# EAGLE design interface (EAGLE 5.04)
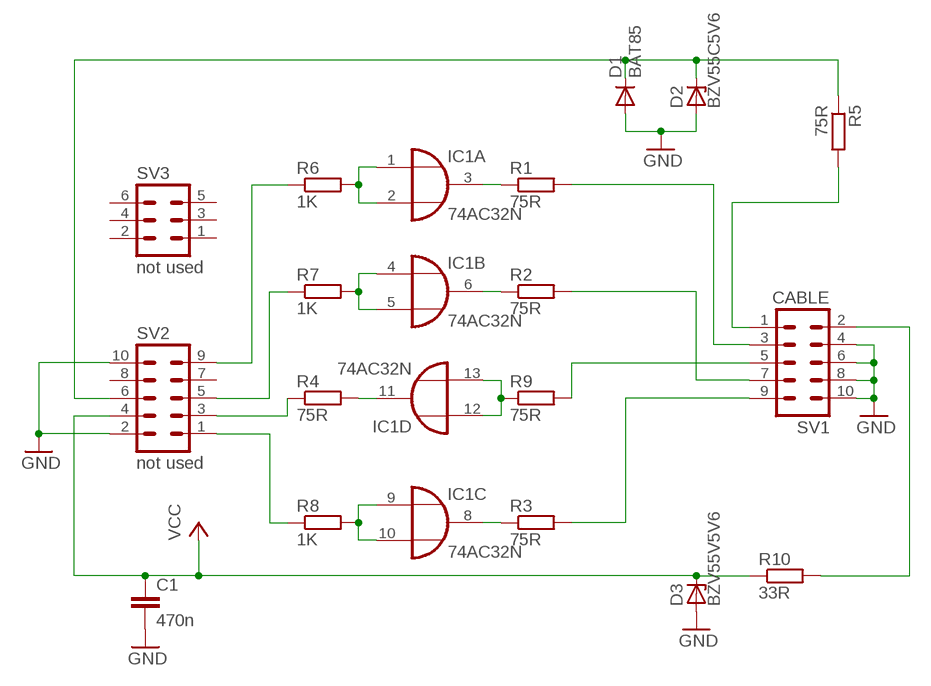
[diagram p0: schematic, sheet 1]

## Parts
C1  470n  C2.5P  [C025-030X050]
D1  BAT85  1N4148  [DO34-7]
D2  BZV55C5V6  ZENERDIODE  [DO34Z7]
D3  BZV55V5V6  ZENERDIODE  [DO34Z7]
IC1  74AC32N  [DIL14]
R1  75R  R  [0207/10]
R2  75R  R  [0207/10]
R3  75R  R  [0207/10]
R4  75R  R  [0207/10]
R5  75R  R  [0207/10]
R6  1K  R  [0207/10]
R7  1K  R  [0207/10]
R8  1K  R  [0207/10]
R9  75R  R  [0207/10]
R10  33R  R  [0207/10]
SV1  CABLE  ML10L  [ML10L]
SV2  not used  MA05-2  [MA05-2]
SV3  not used  MA03-2  [MA03-2]

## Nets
GND: C1.2 D1.A D2.A D3.A SV1.4 SV1.6 SV1.8 SV1.10 SV2.2 SV2.10
N$1: IC1.3(A:O) R1.1
N$2: IC1.6(B:O) R2.1
N$3: IC1.8(C:O) R3.1
N$4: IC1.11(D:O) R4.2
N$5: IC1.4(B:I0) IC1.5(B:I1) R7.2
N$6: IC1.12(D:I0) IC1.13(D:I1) R9.1
N$7: IC1.9(C:I0) IC1.10(C:I1) R8.2
N$8: IC1.1(A:I0) IC1.2(A:I1) R6.2
N$10: D1.C D2.C R5.1 SV2.6
N$11: R5.2 SV1.1
N$12: R1.2 SV1.3
N$13: R2.2 SV1.7
N$14: R3.2 SV1.9
N$16: R9.2 SV1.5
N$17: R6.1 SV2.9
N$18: R7.1 SV2.5
N$19: R4.1 SV2.3
N$20: R8.1 SV2.1
N$21: R10.2 SV1.2
VCC: C1.1 D3.C R10.1 SV2.4
Unconnected: SV2.7 SV2.8 SV3.1 SV3.2 SV3.3 SV3.4 SV3.5 SV3.6

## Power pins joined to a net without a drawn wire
GND: IC1.7(P:GND)
VCC: IC1.14(P:VCC)

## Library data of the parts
C1 = ee2parts:C: Capacitor
D1 = ee2parts:1N4148: DIODE
D2 D3 = ee2parts:ZENERDIODE: Z DIODE
IC1 = 74xx-eu:74*32: Quad 2-input OR gate
R1-R10 = ee2parts:R: Resistor
SV1 = con-ml:ML10L: HARTING
SV2 = con-lstb:MA05-2: PIN HEADER
SV3 = con-lstb:MA03-2: PIN HEADER

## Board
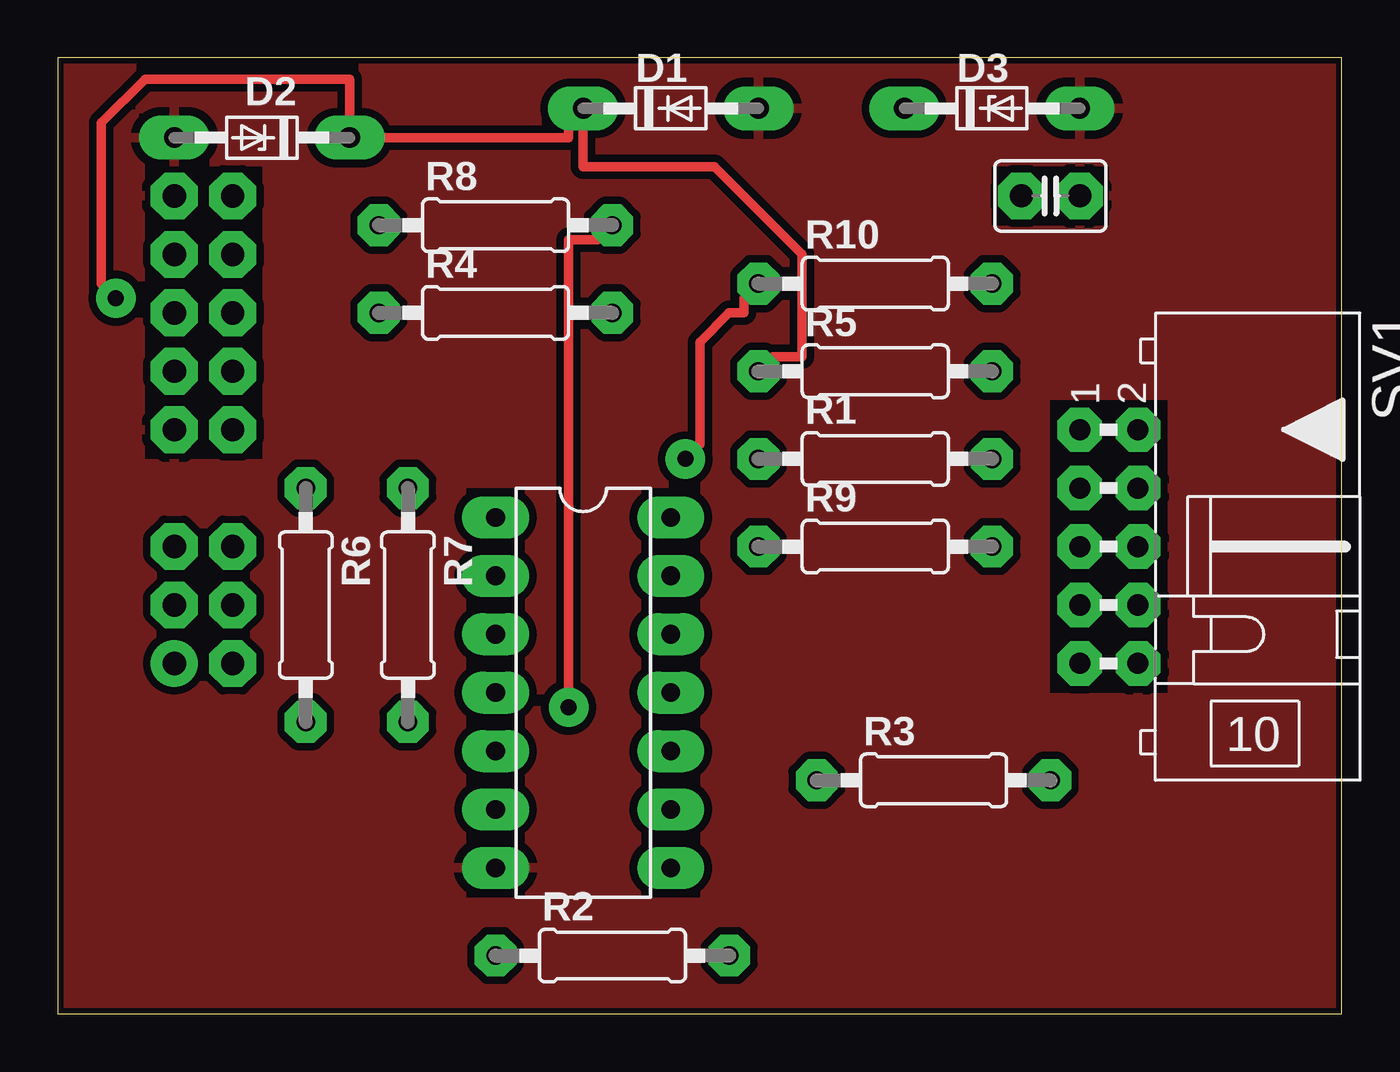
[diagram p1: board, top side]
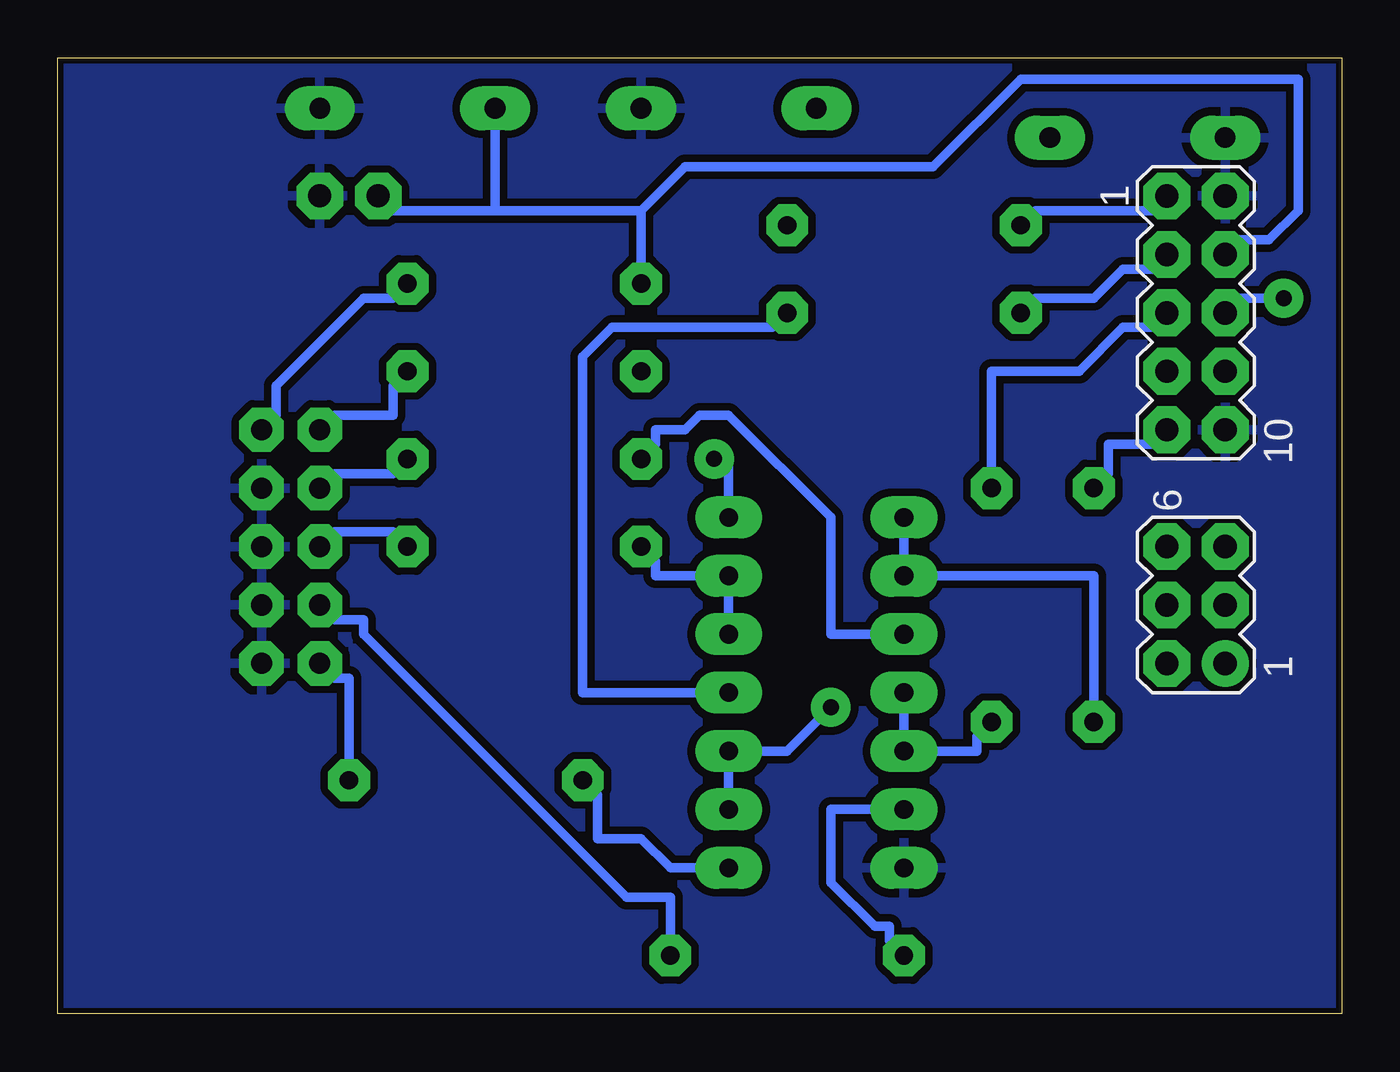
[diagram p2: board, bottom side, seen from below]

Size 55.86 x 41.58 mm. Coordinates in mm from the lower left corner, seen from the top.
Outline: 0,0 55.86,0 55.86,41.58 0,41.58 0,0
Copper layers (1*16): Top 0.035mm / dielectric 1.5mm / Bottom 0.035mm
Design rules "zigbit_rules": minimum track width 16mil, minimum drill 0.7mm, track to track 13mil, track to pad 13mil, pad to pad 13mil, via to via 13mil, smd to smd 0mil, copper to edge 10mil, drill to drill 10mil, minimum pad ring 20mil, minimum via ring 20mil, stop-mask expansion 0mil, vias tented up to drill 0mil, thermal gap 15mil
tRestrict: area 43.2,14 to 48.3,26.7; area 40.6,34.3 to 45.7,36.8; area 17.8,5.1 to 20.3,22.9; area 25.4,5.1 to 27.9,22.9; area 3.8,24.1 to 8.9,36.8
vRestrict: area 47,8.9 to 57.1,31.8

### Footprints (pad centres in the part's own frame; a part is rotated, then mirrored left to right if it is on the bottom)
C025-030X050 = drill 1 octagon: 1 -1.27,0; 2 1.27,0
DO34-7 = drill 0.9 long: A 3.81,0; C -3.81,0
DO34Z7 = drill 0.9 long: A 3.81,0; C -3.81,0
DIL14 = drill 0.813 long: 1 -7.62,-3.81; 2 -5.08,-3.81; 3 -2.54,-3.81; 4 0,-3.81; 5 2.54,-3.81; 6 5.08,-3.81; 7 7.62,-3.81; 8 7.62,3.81; 9 5.08,3.81; 10 2.54,3.81; 11 0,3.81; 12 -2.54,3.81; 13 -5.08,3.81; 14 -7.62,3.81
0207/10 = drill 0.8 octagon: 1 -5.08,0; 2 5.08,0
ML10L = drill 0.914 octagon: 1 -5.08,-1.27; 2 -5.08,1.27; 3 -2.54,-1.27; 4 -2.54,1.27; 5 0,-1.27; 6 0,1.27; 7 2.54,-1.27; 8 2.54,1.27; 9 5.08,-1.27; 10 5.08,1.27
MA05-2 = drill 1.016 octagon: 1 -5.08,-1.27; 2 -5.08,1.27; 3 -2.54,-1.27; 4 -2.54,1.27; 5 0,-1.27; 6 0,1.27; 7 2.54,-1.27; 8 2.54,1.27; 9 5.08,-1.27; 10 5.08,1.27
MA03-2 = drill 1.016 round: 1 -2.54,-1.27 | drill 1.016 octagon: 2 -2.54,1.27; 3 0,-1.27; 4 0,1.27; 5 2.54,-1.27; 6 2.54,1.27

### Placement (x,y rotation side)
C1  43.18,35.56 0 top
D1  26.67,39.37 0 top
D2  8.89,38.1 180 top
D3  40.64,39.37 0 top
IC1  22.86,13.97 270 top
R1  35.56,24.13 0 top
R2  24.13,2.54 0 top
R3  38.1,10.16 0 top
R4  19.05,30.48 0 top
R5  35.56,27.94 0 top
R6  10.8,17.78 270 top
R7  15.24,17.78 270 top
R8  19.05,34.29 0 top
R9  35.56,20.32 0 top
R10  35.56,31.75 0 top
SV1  45.72,20.32 270 top
SV2  6.35,30.48 270 bottom
SV3  6.35,17.78 90 bottom

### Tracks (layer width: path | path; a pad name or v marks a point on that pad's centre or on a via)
GND
  pour Top: 0,41.91 55.88,41.91 55.88,0 0,0
  pour Bottom: 0,41.91 55.88,41.91 55.88,0 0,0
N$1
  Bottom 0.406: R1.1 29.85,24.77 29.85,25.4 28.57,25.4 27.94,26.03 26.67,26.03 22.22,21.59 22.22,16.51 IC1.3
N$2
  Bottom 0.406: R2.1 19.68,3.17 19.68,3.81 20.32,3.81 22.22,5.71 22.22,8.89 IC1.6
N$3
  Bottom 0.406: R3.1 32.39,9.52 32.39,7.62 30.48,7.62 29.21,6.35 IC1.8
N$4
  Bottom 0.406: R4.2 24.77,29.84 31.75,29.84 33.02,28.58 33.02,13.97 IC1.11
N$5
  Bottom 0.406: R7.2 15.88,12.06 15.88,11.43 IC1.5 IC1.4
N$6
  Bottom 0.406: R9.1 29.85,19.69 29.85,19.05 IC1.13 IC1.12
N$7  (via drill 0.7)
  Top 0.406: v22.22,13.34 22.22,33.66 23.5,33.66 R8.2
  Bottom 0.406: v22.22,13.34 24.13,11.43 IC1.10 IC1.9
N$8
  Bottom 0.406: R6.2 10.8,19.05 IC1.2 IC1.1
N$10  (via drill 0.7)
  Top 0.406: R5.1 31.11,28.58 32.39,28.58 32.39,33.02 28.57,36.83 22.86,36.83 D1.C 22.22,38.73 22.22,38.1 D2.C 12.7,40.64 3.81,40.64 1.91,38.73 1.91,31.75 v2.54,31.12
  Bottom 0.406: v2.54,31.12 4.45,31.12 SV2.6
N$11
  Bottom 0.406: R5.2 41.28,27.3 41.28,26.03 43.81,26.03 SV1.1
N$12
  Bottom 0.406: R1.2 41.28,23.49 43.81,23.49 SV1.3
N$13
  Bottom 0.406: R2.2 29.21,5.08 31.11,5.08 42.55,16.51 42.55,17.14 43.81,17.14 SV1.7
N$14
  Bottom 0.406: R3.2 43.18,14.61 43.81,14.61 SV1.9
N$16
  Bottom 0.406: R9.2 41.28,20.95 43.81,20.95 SV1.5
N$17
  Bottom 0.406: R6.1 10.16,23.49 10.16,24.77 8.25,24.77 SV2.9
N$18
  Bottom 0.406: R7.1 15.24,27.94 11.43,27.94 9.53,29.84 8.25,29.84 SV2.5
N$19
  Bottom 0.406: R4.1 13.34,31.12 10.8,31.12 9.53,32.38 8.25,32.38 SV2.3
N$20
  Bottom 0.406: R8.1 13.34,34.92 8.25,34.92 SV2.1
N$21
  Bottom 0.406: R10.2 41.28,31.12 42.55,31.12 46.36,27.3 46.36,26.03 SV1.2
VCC  (via drill 0.7)
  Top 0.406: v27.31,24.13 27.94,24.77 27.94,29.21 29.21,30.48 29.85,30.48 29.85,31.12 R10.1
  Bottom 0.406: 36.83,34.92 41.28,34.92 C1.1 | 30.48,34.92 36.83,34.92 | 30.48,34.92 R10.1 | v27.31,24.13 26.67,24.13 IC1.14 | 36.83,34.92 D3.C | 30.48,34.92 28.57,36.83 17.78,36.83 13.97,40.64 1.91,40.64 1.91,34.92 3.18,33.66 4.45,33.66 SV2.4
